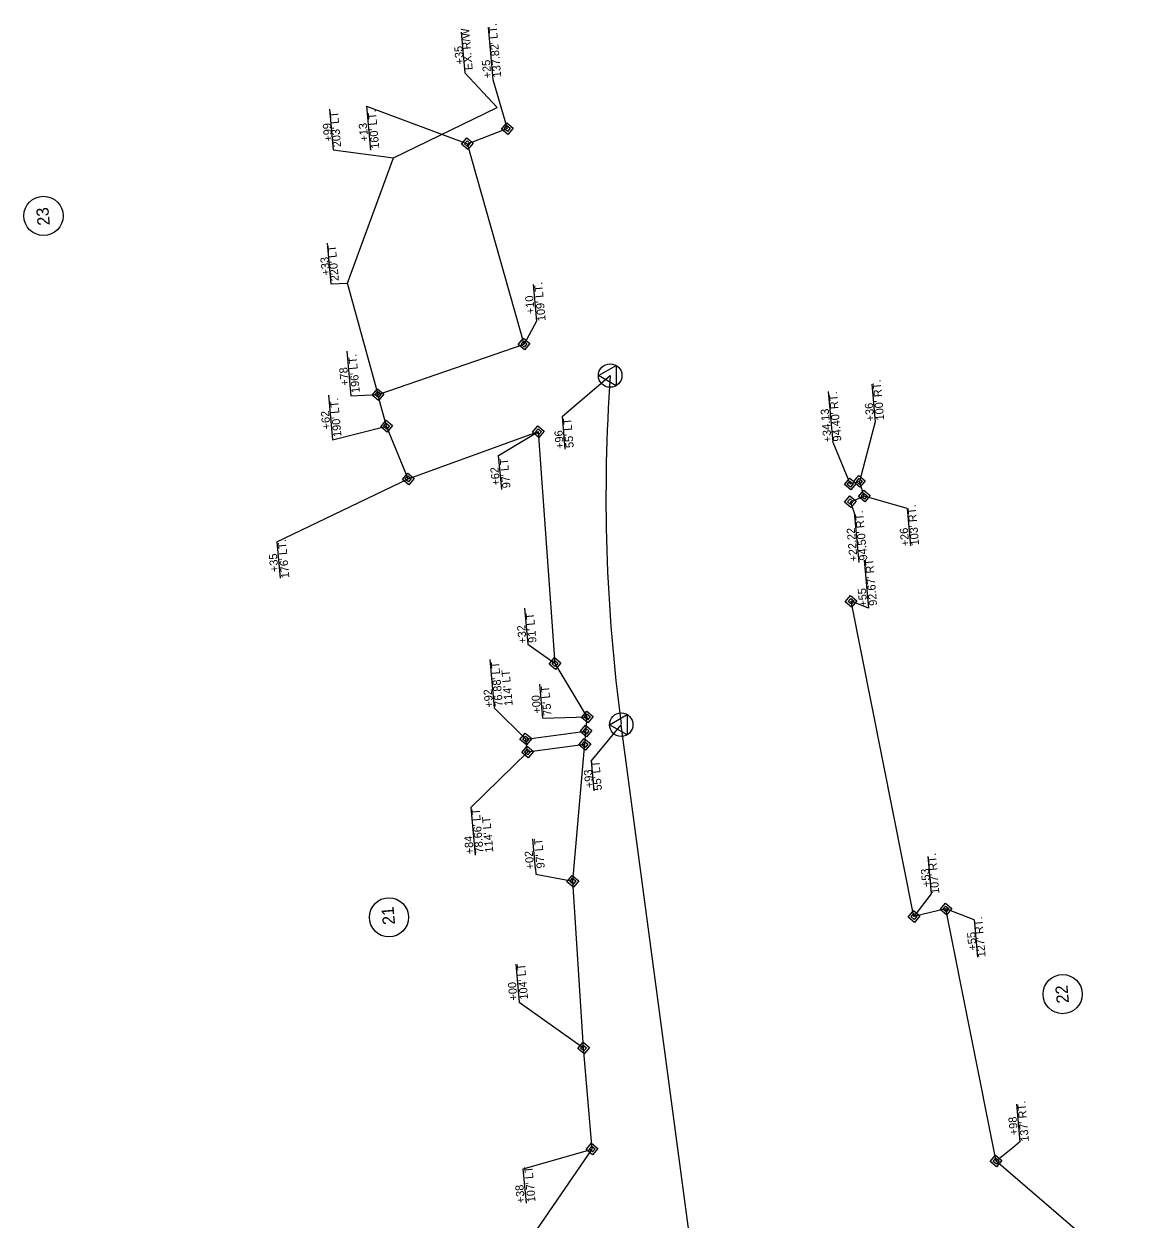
# Model space of a CAD drawing. Extents: x 1555582 to 1558054, y 687961 to 694065.
# Drawn here: x 1555582 to 1556266, y 693334 to 694065 of the extents above; entities that cross this region are included whole.
import ezdxf

# ---------------------------------------------------------------- set-up
doc = ezdxf.new("R2010")
doc.units = 0
for name, color, linetype in [('Exist Horizontal Alignment', 7, 'Continuous'), ('Exist Hydrographic FEMA Cross Section', 7, 'Continuous'), ('Exist Structure Major Bridge Seam', 7, 'Continuous'), ('Exist Structure Minor Drop Inlet Text', 7, 'Continuous'), ('Prop Approach Slab Hatching', 7, 'Continuous'), ('Prop Drainage Structure Box Reinforced Concrete', 7, 'Continuous'), ('Prop Drainage Structure Catch Basin Grate 840 03F Label', 7, 'Continuous'), ('Prop Drainage Structure Catch Basin Grate 840 03G CELL', 7, 'Continuous'), ('Prop Drainage Structure Plot Symbol 50 Scale', 7, 'Continuous'), ('Prop Erosion Rip Rap Class II', 7, 'Continuous'), ('Prop Plan Preparation Excavation Hatching', 7, 'Continuous'), ('Scratch_Level_3', 7, 'Continuous')]:
    doc.layers.add(name, color=color, linetype=linetype)

msp = doc.modelspace()

# ---------------------------------------------------------------- linework, layer by layer
at = {"layer": 'Exist Horizontal Alignment'}
for p, q in [((1555911.47, 693825.09), (1555913.26, 693805.19)), ((1555929.3, 693614.19), (1555930.94, 693596.03))]:
    msp.add_line(p, q, dxfattribs=at)
for points in [[(1555911.47, 693825.09), (1555940.93, 693850.19)], [(1555929.3, 693614.19), (1555947.69, 693636.52)]]:
    msp.add_lwpolyline(points, dxfattribs=at)
at = {"layer": 'Exist Hydrographic FEMA Cross Section'}
msp.add_line((1556081.7, 692632.42), (1555947.69, 693636.52), dxfattribs=at)
msp.add_arc((1556993.36, 693776.51), 1055, 175.99551, 187.60209, dxfattribs=at)
at = {"layer": 'Exist Structure Major Bridge Seam'}
for p, q in [((1556074.4, 693840.4), (1556077.18, 693809.52)), ((1556101.02, 693844.88), (1556103.09, 693821.94)), ((1556090.26, 693766.62), (1556093.04, 693735.75)), ((1556122.7, 693768.93), (1556124.76, 693745.99)), ((1555867.34, 693676.5), (1555870.01, 693646.87)), ((1555855.64, 693585.95), (1555858.27, 693556.78))]:
    msp.add_line(p, q, dxfattribs=at)
for points in [[(1556103.09, 693821.94), (1556093.4, 693785.41)], [(1556077.18, 693809.52), (1556087.79, 693783.78)], [(1556122.7, 693768.93), (1556096.36, 693776.41)], [(1556090.26, 693766.62), (1556087.87, 693772.99)], [(1555870.01, 693646.87), (1555889.34, 693627.72)], [(1555855.64, 693585.95), (1555890.4, 693619.79)]]:
    msp.add_lwpolyline(points, dxfattribs=at)
at = {"layer": 'Exist Structure Minor Drop Inlet Text'}
for p, q in [((1555849.73, 694060.3), (1555851.97, 694035.49)), ((1555769.26, 694013.16), (1555771.49, 693988.35)), ((1555767.87, 693931.18), (1555770.11, 693906.36))]:
    msp.add_line(p, q, dxfattribs=at)
for points in [[(1555851.97, 694035.49), (1555871.76, 694014.27)], [(1555771.49, 693988.35), (1555808.29, 693983.47)], [(1555770.11, 693906.36), (1555780.32, 693906.67)]]:
    msp.add_lwpolyline(points, dxfattribs=at)
at = {"layer": 'Prop Approach Slab Hatching'}
for p, q in [((1555877.97, 694001.33), (1555877.97, 694001.33)), ((1555853.56, 693992.05), (1555853.56, 693992.05)), ((1555888.26, 693869.44), (1555888.26, 693869.44)), ((1555798.97, 693838.55), (1555798.97, 693838.55)), ((1555804.13, 693819.21), (1555804.13, 693819.21)), ((1555897.07, 693815.88), (1555897.07, 693815.88)), ((1555817.41, 693786.97), (1555817.41, 693786.97)), ((1556087.79, 693783.78), (1556087.79, 693783.78)), ((1556093.4, 693785.41), (1556093.4, 693785.41)), ((1556096.36, 693776.41), (1556096.36, 693776.41)), ((1556087.87, 693772.99), (1556087.87, 693772.99)), ((1556088.32, 693712.05), (1556088.32, 693712.05)), ((1555907.19, 693673.99), (1555907.19, 693673.99)), ((1555926.9, 693641.3), (1555926.9, 693641.3)), ((1555889.34, 693627.72), (1555889.34, 693627.72)), ((1555926.14, 693632.63), (1555926.14, 693632.63)), ((1555925.42, 693624.47), (1555925.42, 693624.47)), ((1555890.4, 693619.79), (1555890.4, 693619.79)), ((1555918.1, 693540.76), (1555918.1, 693540.76)), ((1556126.78, 693519.18), (1556126.78, 693519.18)), ((1556146.34, 693523.81), (1556146.34, 693523.81)), ((1555924.65, 693438.73), (1555924.65, 693438.73)), ((1555929.88, 693376.88), (1555929.88, 693376.88)), ((1556177.03, 693369.51), (1556177.03, 693369.51))]:
    msp.add_line(p, q, dxfattribs=at)
at = {"layer": 'Prop Drainage Structure Box Reinforced Concrete'}
for p, q in [((1555808.29, 693983.47), (1555871.76, 694014.27)), ((1555780.32, 693906.67), (1555808.29, 693983.47)), ((1555798.97, 693838.55), (1555780.32, 693906.67))]:
    msp.add_line(p, q, dxfattribs=at)
at = {"layer": 'Prop Drainage Structure Catch Basin Grate 840 03F Label'}
for p, q in [((1555594.27, 693947.88), (1555594.27, 693947.88)), ((1555805.6, 693518.67), (1555805.6, 693518.67)), ((1556217.76, 693471.7), (1556217.76, 693471.7))]:
    msp.add_line(p, q, dxfattribs=at)
for centre in [(1555594.27, 693947.88), (1555805.6, 693518.67), (1556217.76, 693471.7)]:
    msp.add_circle(centre, 12, dxfattribs=at)
at = {"layer": 'Prop Drainage Structure Plot Symbol 50 Scale'}
for p, q in [((1555866.27, 694063.25), (1555869.14, 694031.38)), ((1555791.8, 694014.96), (1555794.22, 693988.05)), ((1555893.84, 693905.87), (1555895.85, 693883.53)), ((1555779.88, 693865.04), (1555782.34, 693837.71)), ((1555940.93, 693850.19), (1555940.93, 693850.19)), ((1555768.66, 693838.11), (1555771.12, 693810.78)), ((1555872.7, 693801.35), (1555897.07, 693815.88)), ((1555874.58, 693780.5), (1555872.7, 693801.35)), ((1555737.05, 693748.51), (1555739.06, 693726.16)), ((1556096.37, 693737.32), (1556099.02, 693707.87)), ((1555888.54, 693707.8), (1555890.51, 693685.88)), ((1555899.72, 693640.57), (1555897.86, 693661.29)), ((1555899.72, 693640.57), (1555926.9, 693641.3)), ((1555947.69, 693636.52), (1555947.69, 693636.52)), ((1555895.24, 693548.33), (1555893.59, 693566.74)), ((1556135.27, 693555.99), (1556137.34, 693533.06)), ((1556163.56, 693517.18), (1556165.62, 693494.25)), ((1556189.44, 693404.32), (1556191.5, 693381.38)), ((1555887.8, 693364.72), (1555929.88, 693376.88)), ((1555889.69, 693343.66), (1555887.8, 693364.72))]:
    msp.add_line(p, q, dxfattribs=at)
for points in [[(1555869.14, 694031.38), (1555877.97, 694001.33)], [(1555791.8, 694014.96), (1555853.56, 693992.05)], [(1555895.85, 693883.53), (1555888.26, 693869.44)], [(1555782.34, 693837.71), (1555798.97, 693838.55)], [(1555771.12, 693810.78), (1555804.13, 693819.21)], [(1555737.05, 693748.51), (1555817.41, 693786.97)], [(1556099.02, 693707.87), (1556088.32, 693712.05)], [(1555890.51, 693685.88), (1555907.19, 693673.99)], [(1555895.24, 693548.33), (1555895.53, 693545.11), (1555918.1, 693540.76)], [(1556137.34, 693533.06), (1556126.78, 693519.18)], [(1556163.56, 693517.18), (1556146.34, 693523.81)], [(1555883.16, 693490.05), (1555885.25, 693466.84), (1555924.65, 693438.73)], [(1556191.5, 693381.38), (1556187.28, 693377.62), (1556177.03, 693369.51)]]:
    msp.add_lwpolyline(points, dxfattribs=at)
for points in [[(1555944.53, 693843.93), (1555933.73, 693850.2), (1555944.54, 693856.43)], [(1555951.28, 693630.27), (1555940.49, 693636.53), (1555951.3, 693642.77)]]:
    msp.add_lwpolyline(points, close=True, dxfattribs=at)
for centre in [(1555940.93, 693850.19), (1555947.69, 693636.52)]:
    msp.add_circle(centre, 7.2, dxfattribs=at)
at = {"layer": 'Prop Erosion Rip Rap Class II'}
for p, q in [((1556093.4, 693785.41), (1556087.79, 693783.78)), ((1556096.36, 693776.41), (1556093.4, 693785.41)), ((1556087.87, 693772.99), (1556096.36, 693776.41)), ((1555889.34, 693627.72), (1555926.14, 693632.63)), ((1555890.4, 693619.79), (1555889.34, 693627.72)), ((1555925.42, 693624.47), (1555890.4, 693619.79))]:
    msp.add_line(p, q, dxfattribs=at)
at = {"layer": 'Prop Plan Preparation Excavation Hatching'}
for p, q in [((1555853.56, 693992.05), (1555877.97, 694001.33)), ((1555888.26, 693869.44), (1555853.56, 693992.05)), ((1555798.97, 693838.55), (1555888.26, 693869.44)), ((1555804.13, 693819.21), (1555798.86, 693838.55)), ((1555817.41, 693786.97), (1555804.13, 693819.21)), ((1555817.41, 693786.97), (1555897.07, 693815.88)), ((1555907.19, 693673.99), (1555897.07, 693815.88)), ((1556126.78, 693519.18), (1556088.32, 693712.05)), ((1555926.9, 693641.3), (1555907.19, 693673.99)), ((1555918.1, 693540.76), (1555926.9, 693641.3)), ((1555924.65, 693438.73), (1555918.1, 693540.76)), ((1556146.34, 693523.81), (1556126.78, 693519.18)), ((1556177.03, 693369.51), (1556146.34, 693523.81)), ((1555929.88, 693376.88), (1555924.65, 693438.73)), ((1555816.15, 693211.38), (1555929.88, 693376.88)), ((1556265.74, 693293.28), (1556177.03, 693369.51))]:
    msp.add_line(p, q, dxfattribs=at)
at = {"layer": 'Scratch_Level_3'}
for points in [[(1555874.38, 694001), (1555877.64, 694004.91), (1555881.55, 694001.65), (1555878.29, 693997.74)], [(1555876.17, 694001.17), (1555877.8, 694003.12), (1555879.76, 694001.49), (1555878.13, 693999.53)], [(1555849.97, 693991.72), (1555853.24, 693995.63), (1555857.14, 693992.37), (1555853.88, 693988.46)], [(1555851.77, 693991.89), (1555853.4, 693993.84), (1555855.35, 693992.21), (1555853.72, 693990.25)], [(1555884.67, 693869.12), (1555887.94, 693873.02), (1555891.84, 693869.76), (1555888.58, 693865.85)], [(1555886.47, 693869.28), (1555888.1, 693871.23), (1555890.05, 693869.6), (1555888.42, 693867.65)], [(1555795.38, 693838.22), (1555798.65, 693842.13), (1555802.55, 693838.87), (1555799.29, 693834.96)], [(1555797.18, 693838.39), (1555798.81, 693840.34), (1555800.76, 693838.71), (1555799.13, 693836.75)], [(1555800.54, 693818.89), (1555803.8, 693822.8), (1555807.71, 693819.54), (1555804.45, 693815.63)], [(1555802.33, 693819.05), (1555803.96, 693821.01), (1555805.92, 693819.38), (1555804.29, 693817.42)], [(1555893.48, 693815.55), (1555896.74, 693819.46), (1555900.65, 693816.2), (1555897.39, 693812.29)], [(1555895.27, 693815.72), (1555896.9, 693817.67), (1555898.86, 693816.04), (1555897.23, 693814.08)], [(1555813.82, 693786.65), (1555817.08, 693790.55), (1555820.99, 693787.29), (1555817.73, 693783.38)], [(1555815.61, 693786.81), (1555817.24, 693788.76), (1555819.2, 693787.13), (1555817.57, 693785.18)], [(1556089.82, 693785.09), (1556093.08, 693789), (1556096.99, 693785.74), (1556093.73, 693781.83)], [(1556084.2, 693783.46), (1556087.46, 693787.36), (1556091.37, 693784.1), (1556088.11, 693780.19)], [(1556085.99, 693783.62), (1556087.63, 693785.57), (1556089.58, 693783.94), (1556087.95, 693781.99)], [(1556091.61, 693785.25), (1556093.24, 693787.21), (1556095.2, 693785.58), (1556093.56, 693783.62)], [(1556084.28, 693772.67), (1556087.54, 693776.58), (1556091.45, 693773.31), (1556088.19, 693769.41)], [(1556086.07, 693772.83), (1556087.71, 693774.78), (1556089.66, 693773.15), (1556088.03, 693771.2)], [(1556092.77, 693776.09), (1556096.04, 693780), (1556099.94, 693776.74), (1556096.68, 693772.83)], [(1556094.57, 693776.25), (1556096.2, 693778.21), (1556098.15, 693776.58), (1556096.52, 693774.62)], [(1556084.73, 693711.72), (1556088, 693715.63), (1556091.9, 693712.37), (1556088.64, 693708.46)], [(1556086.53, 693711.89), (1556088.16, 693713.84), (1556090.11, 693712.21), (1556088.48, 693710.25)], [(1555903.6, 693673.67), (1555906.86, 693677.58), (1555910.77, 693674.31), (1555907.51, 693670.41)], [(1555905.39, 693673.83), (1555907.03, 693675.78), (1555908.98, 693674.15), (1555907.35, 693672.2)], [(1555923.31, 693640.98), (1555926.57, 693644.89), (1555930.48, 693641.63), (1555927.22, 693637.72)], [(1555925.1, 693641.14), (1555926.73, 693643.1), (1555928.69, 693641.47), (1555927.06, 693639.51)], [(1555922.55, 693632.31), (1555925.81, 693636.22), (1555929.72, 693632.96), (1555926.46, 693629.05)], [(1555885.75, 693627.4), (1555889.02, 693631.31), (1555892.92, 693628.05), (1555889.66, 693624.14)], [(1555887.55, 693627.56), (1555889.18, 693629.52), (1555891.13, 693627.88), (1555889.5, 693625.93)], [(1555921.84, 693624.15), (1555925.1, 693628.05), (1555929.01, 693624.79), (1555925.74, 693620.88)], [(1555924.34, 693632.47), (1555925.98, 693634.43), (1555927.93, 693632.8), (1555926.3, 693630.84)], [(1555886.81, 693619.47), (1555890.07, 693623.38), (1555893.98, 693620.12), (1555890.72, 693616.21)], [(1555888.6, 693619.63), (1555890.24, 693621.59), (1555892.19, 693619.96), (1555890.56, 693618)], [(1555923.63, 693624.31), (1555925.26, 693626.26), (1555927.21, 693624.63), (1555925.58, 693622.68)], [(1555914.51, 693540.44), (1555917.77, 693544.35), (1555921.68, 693541.09), (1555918.42, 693537.18)], [(1555916.3, 693540.6), (1555917.93, 693542.56), (1555919.89, 693540.92), (1555918.26, 693538.97)], [(1556142.76, 693523.49), (1556146.02, 693527.4), (1556149.93, 693524.13), (1556146.67, 693520.22)], [(1556144.55, 693523.65), (1556146.18, 693525.6), (1556148.14, 693523.97), (1556146.51, 693522.02)], [(1556123.2, 693518.86), (1556126.46, 693522.77), (1556130.37, 693519.5), (1556127.11, 693515.6)], [(1556124.99, 693519.02), (1556126.62, 693520.97), (1556128.58, 693519.34), (1556126.95, 693517.39)], [(1555921.07, 693438.41), (1555924.33, 693442.32), (1555928.24, 693439.06), (1555924.97, 693435.15)], [(1555922.86, 693438.57), (1555924.49, 693440.53), (1555926.44, 693438.9), (1555924.81, 693436.94)], [(1555926.29, 693376.56), (1555929.56, 693380.47), (1555933.46, 693377.2), (1555930.2, 693373.3)], [(1555928.09, 693376.72), (1555929.72, 693378.67), (1555931.67, 693377.04), (1555930.04, 693375.09)], [(1556173.44, 693369.19), (1556176.7, 693373.1), (1556180.61, 693369.84), (1556177.35, 693365.93)], [(1556175.23, 693369.35), (1556176.87, 693371.31), (1556178.82, 693369.67), (1556177.19, 693367.72)]]:
    msp.add_lwpolyline(points, close=True, dxfattribs=at)

# ---------------------------------------------------------------- texts
at = {"layer": 'Exist Horizontal Alignment'}
for s, p in [("55' LT", (1555918.71, 693806.1)), ('+96', (1555912.73, 693805.56)), ("55' LT", (1555935.94, 693596.46)), ('+93', (1555930.73, 693598.02))]:
    msp.add_text(s, height=5, rotation=95.14143, dxfattribs=at).set_placement(p)
at = {"layer": 'Exist Structure Major Bridge Seam'}
for s, p in [("100' RT.", (1556108.6, 693822.97)), ("94.40' RT.", (1556082.43, 693810.08)), ('+36', (1556102.62, 693822.43)), ('+34.13', (1556076.45, 693809.54)), ("94.50' RT.", (1556098.33, 693737.2)), ("103' RT.", (1556129.95, 693746.5)), ('+22.22', (1556092.35, 693736.66)), ('+26', (1556123.98, 693745.96)), ("76.88' LT ", (1555875.38, 693647.75)), ("114' LT", (1555881.35, 693648.29)), ('+92', (1555869.4, 693647.21)), ("78.66' LT", (1555863.51, 693558)), ("114' LT", (1555869.48, 693558.53)), ('+84', (1555857.53, 693557.46))]:
    msp.add_text(s, height=5, rotation=95.14143, dxfattribs=at).set_placement(p)
at = {"layer": 'Exist Structure Minor Drop Inlet Text'}
for s, p in [('EX. R/W ', (1555856.84, 694037.34)), ('+35', (1555851.46, 694040.79)), ("203' LT ", (1555776.38, 693990.14)), ('+99', (1555771, 693993.6)), ("220' LT ", (1555774.99, 693908.15)), ('+33', (1555769.6, 693911.68))]:
    msp.add_text(s, height=5, rotation=95.14143, dxfattribs=at).set_placement(p)
at = {"layer": 'Prop Drainage Structure Catch Basin Grate 840 03G CELL'}
for s, p in [('23', (1555598.18, 693942.3)), ('21', (1555809.38, 693514.41)), ('22', (1556221.64, 693466.37))]:
    msp.add_text(s, height=7.5, rotation=95.14143, dxfattribs=at).set_placement(p)
at = {"layer": 'Prop Drainage Structure Plot Symbol 50 Scale'}
for s, p in [("137.82' LT.", (1555874.32, 694032.86)), ('+25', (1555868.35, 694032.32)), ("160' LT.", (1555799.69, 693989.2)), ('+13', (1555793.02, 693993.61)), ("109' LT.", (1555901.48, 693883.75)), ('+10', (1555894.81, 693888.04)), (" 196' LT.", (1555787.97, 693837.94)), ('+78', (1555781.13, 693844.13)), (" 190' LT.", (1555776.75, 693811.01)), ('+62', (1555769.89, 693817.47)), ("97' LT", (1555879.96, 693781.47)), ('+62', (1555873.54, 693783.08)), ("176' LT.", (1555744.69, 693726.38)), ('+35', (1555738.07, 693730.18)), ("92.67' RT", (1556104.3, 693709.55)), ('+55', (1556098.32, 693709.01)), ("91' LT", (1555895.88, 693686.9)), ('+32', (1555889.91, 693686.36)), ("75' LT", (1555905.13, 693642.21)), ('+00', (1555898.73, 693643.56)), ("97' LT", (1555900.97, 693548.84)), ('+02', (1555894.5, 693548.26)), ("107' RT.", (1556142.37, 693533.22)), ('+53', (1556136.92, 693537.43)), ("127' RT.", (1556170.65, 693494.41)), ('+55', (1556165.21, 693498.61)), ("104' LT", (1555890.75, 693468.57)), ('+00', (1555884.28, 693467.99)), ("137' RT.", (1556197.13, 693381.6)), ('+98', (1556190.49, 693385.6)), ("107' LT", (1555895.28, 693344.55)), ('+38', (1555888.8, 693343.97))]:
    msp.add_text(s, height=5, rotation=95.14143, dxfattribs=at).set_placement(p)

doc.saveas('drawing.dxf')
